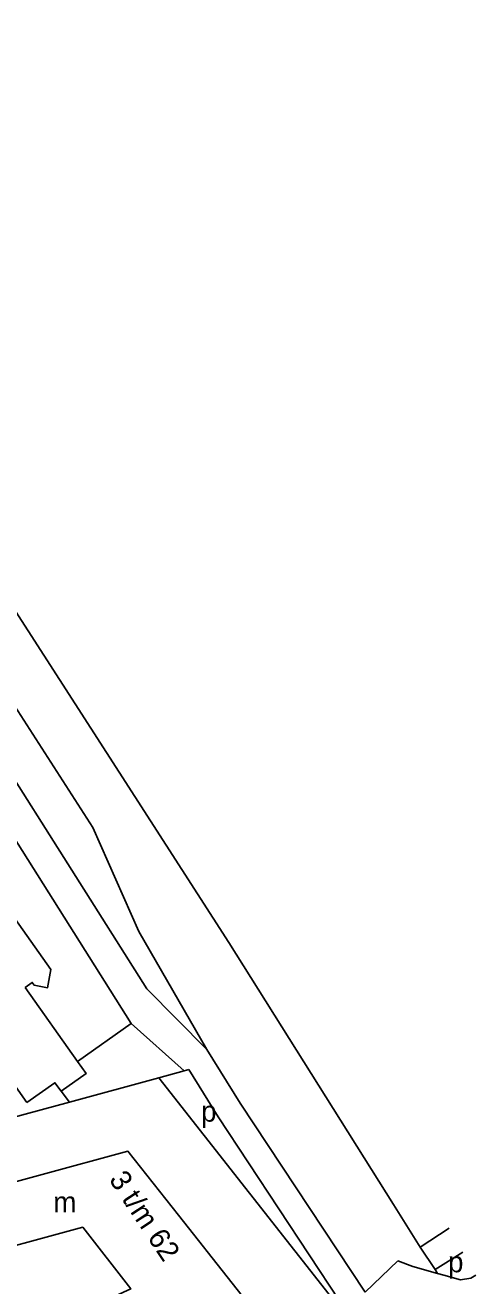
# Model space of a CAD drawing. Extents: x 158848 to 160613, y 385889 to 387762.
# Drawn here: x 160280.6 to 160367.2, y 386850.2 to 387092.9 of the extents above; entities that cross this region are included whole.
import ezdxf

# ---------------------------------------------------------------- set-up
doc = ezdxf.new("R2010")
doc.units = 0
for name, color, linetype in [('BLT_Basislijn', 7, 'Continuous'), ('BLT_Bebouwing', 7, 'Continuous'), ('BLT_Centroide', 7, 'Continuous'), ('BLT_Huisnummer_reeks', 7, 'Continuous'), ('BLT_Vlakafsluiter', 7, 'Continuous')]:
    doc.layers.add(name, color=color, linetype=linetype)

msp = doc.modelspace()

# ---------------------------------------------------------------- linework, layer by layer
at = {"layer": 'BLT_Basislijn'}
for p, q in [((160206.02, 387092.88), (160319.76, 386916.3)), ((160197.58, 387087.5), (160293.61, 386938.43)), ((160268.41, 386963.66), (160303.95, 386907.35)), ((160303.95, 386907.35), (160315.52, 386895.7)), ((160300.98, 386900.72), (160290.62, 386893.4)), ((160300.98, 386900.72), (160311.13, 386891.57)), ((160306.29, 386890.22), (160311.13, 386891.57)), ((160311.13, 386891.57), (160312.04, 386891.83)), ((160306.29, 386890.22), (160289.08, 386885.54)), ((160341.16, 386845.85), (160306.29, 386890.22)), ((160289.08, 386885.54), (160273.44, 386881.29)), ((160289.08, 386885.54), (160287.46, 386887.65)), ((160356.5, 386857.65), (160351.38, 386865.82)), ((160356.5, 386857.65), (160362.11, 386861.27)), ((160356.5, 386857.65), (160359.39, 386853.33)), ((160364.72, 386856.66), (160359.39, 386853.33)), ((160359.85, 386852.59), (160361.06, 386852.25))]:
    msp.add_line(p, q, dxfattribs=at)
for points in [[(160229.4, 386958.18), (160233.73, 386961.36), (160249.99, 386972.42), (160253.87, 386974.98), (160254.18, 386974.92), (160300.98, 386900.72)], [(160293.61, 386938.43), (160302.41, 386918.41), (160315.52, 386895.7)], [(160351.38, 386865.82), (160319.76, 386916.3)], [(160345.92, 386848.96), (160321.89, 386885.38), (160315.52, 386895.7)], [(160341.16, 386845.85), (160341.04, 386847.28), (160317.68, 386882.69), (160312.04, 386891.83)], [(160359.39, 386853.33), (160359.85, 386852.59)], [(160361.06, 386852.25), (160364.3, 386851.33), (160366.24, 386851.64), (160367.22, 386852.26)]]:
    msp.add_lwpolyline(points, dxfattribs=at)
at = {"layer": 'BLT_Bebouwing'}
msp.add_line((160280.59, 386907.61), (160290.62, 386893.4), dxfattribs=at)
for points in [[(160280.89, 386885.46), (160267.35, 386904.64), (160267.6, 386904.82), (160248.07, 386932.49), (160247.84, 386932.33), (160234.3, 386951.52)], [(160280.59, 386907.61), (160281.92, 386908.59), (160282.29, 386908.08), (160284.89, 386907.58), (160285.51, 386911.06), (160259.92, 386947.3), (160256.44, 386947.86), (160256, 386945.34), (160256.4, 386944.77), (160255.04, 386943.86)], [(160290.62, 386893.4), (160292.29, 386891.04), (160287.46, 386887.65)], [(160287.46, 386887.65), (160286.3, 386889.29), (160280.89, 386885.46)], [(160234.37, 386858.16), (160300.33, 386876.09), (160310.03, 386863.78)], [(160310.03, 386863.78), (160330.67, 386837.59), (160333.24, 386834.33)]]:
    msp.add_lwpolyline(points, dxfattribs=at)
msp.add_lwpolyline([(160244.56, 386848.67), (160257.55, 386829.86), (160300.86, 386849.59), (160291.65, 386861.46)], close=True, dxfattribs=at)
at = {"layer": 'BLT_Vlakafsluiter'}
msp.add_line((160345.92, 386848.96), (160352.26, 386854.99), dxfattribs=at)
msp.add_lwpolyline([(160352.26, 386854.99), (160355.14, 386853.9), (160359.85, 386852.59)], dxfattribs=at)

# ---------------------------------------------------------------- texts
at = {"layer": 'BLT_Centroide'}
for s, p in [('p', (160314.39, 386881.79)), ('m', (160285.97, 386864.31)), ('p', (160361.88, 386852.79))]:
    msp.add_text(s, height=4, dxfattribs=at).set_placement(p)
at = {"layer": 'BLT_Huisnummer_reeks'}
msp.add_text('3 t/m 62', height=4, rotation=303.5058, dxfattribs=at).set_placement((160296.57, 386870.66))

doc.saveas('drawing.dxf')
